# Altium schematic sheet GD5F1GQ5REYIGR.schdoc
size 127 x 101 mm
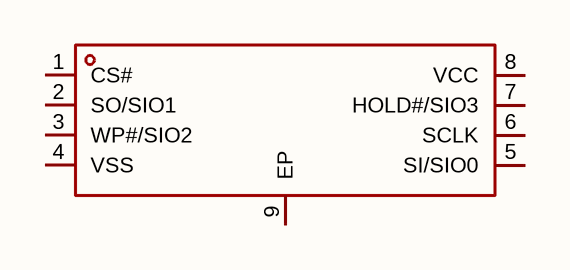
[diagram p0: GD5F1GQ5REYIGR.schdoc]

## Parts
U?  gd5f1gq5reyigr  [WSON-8_L8.0-W6.0-P1.27-TL-1]  (value not drawn)

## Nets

Not connected (* = marked no-connect by the designer): U? 1(CS#) 2(SO/SIO1) 3(WP#/SIO2) 4(VSS) 5(SI/SIO0) 6(SCLK) 7(HOLD#/SIO3) 8(VCC) 9(EP)

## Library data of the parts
U? = gd5f1gq5reyigr: 存储容量:1Gbit;时钟频率(fc):104MHz;工作电压:1.7V~2V;; Manufacturer: GigaDevice(兆易创新); AddInBom: yes; ModelId: f7358afd81b248ccb497b4df88085798; ModelTransform: 315.7474,236.22,0,0,0,0,0,0,0; Memory Size: 1Gbit; Interface: SPI; Clock Frequency: 104MHz; Page Program time (TPP): 400us; Block Erase Time(tBE): 3ms; Data Retention - TDR (Year): 10年; Standby Supply Current: 50uA; Program / Erase Cycles: 10万次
